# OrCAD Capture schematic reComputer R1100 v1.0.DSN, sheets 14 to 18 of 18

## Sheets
14 16 Gigabit PoE: size A3
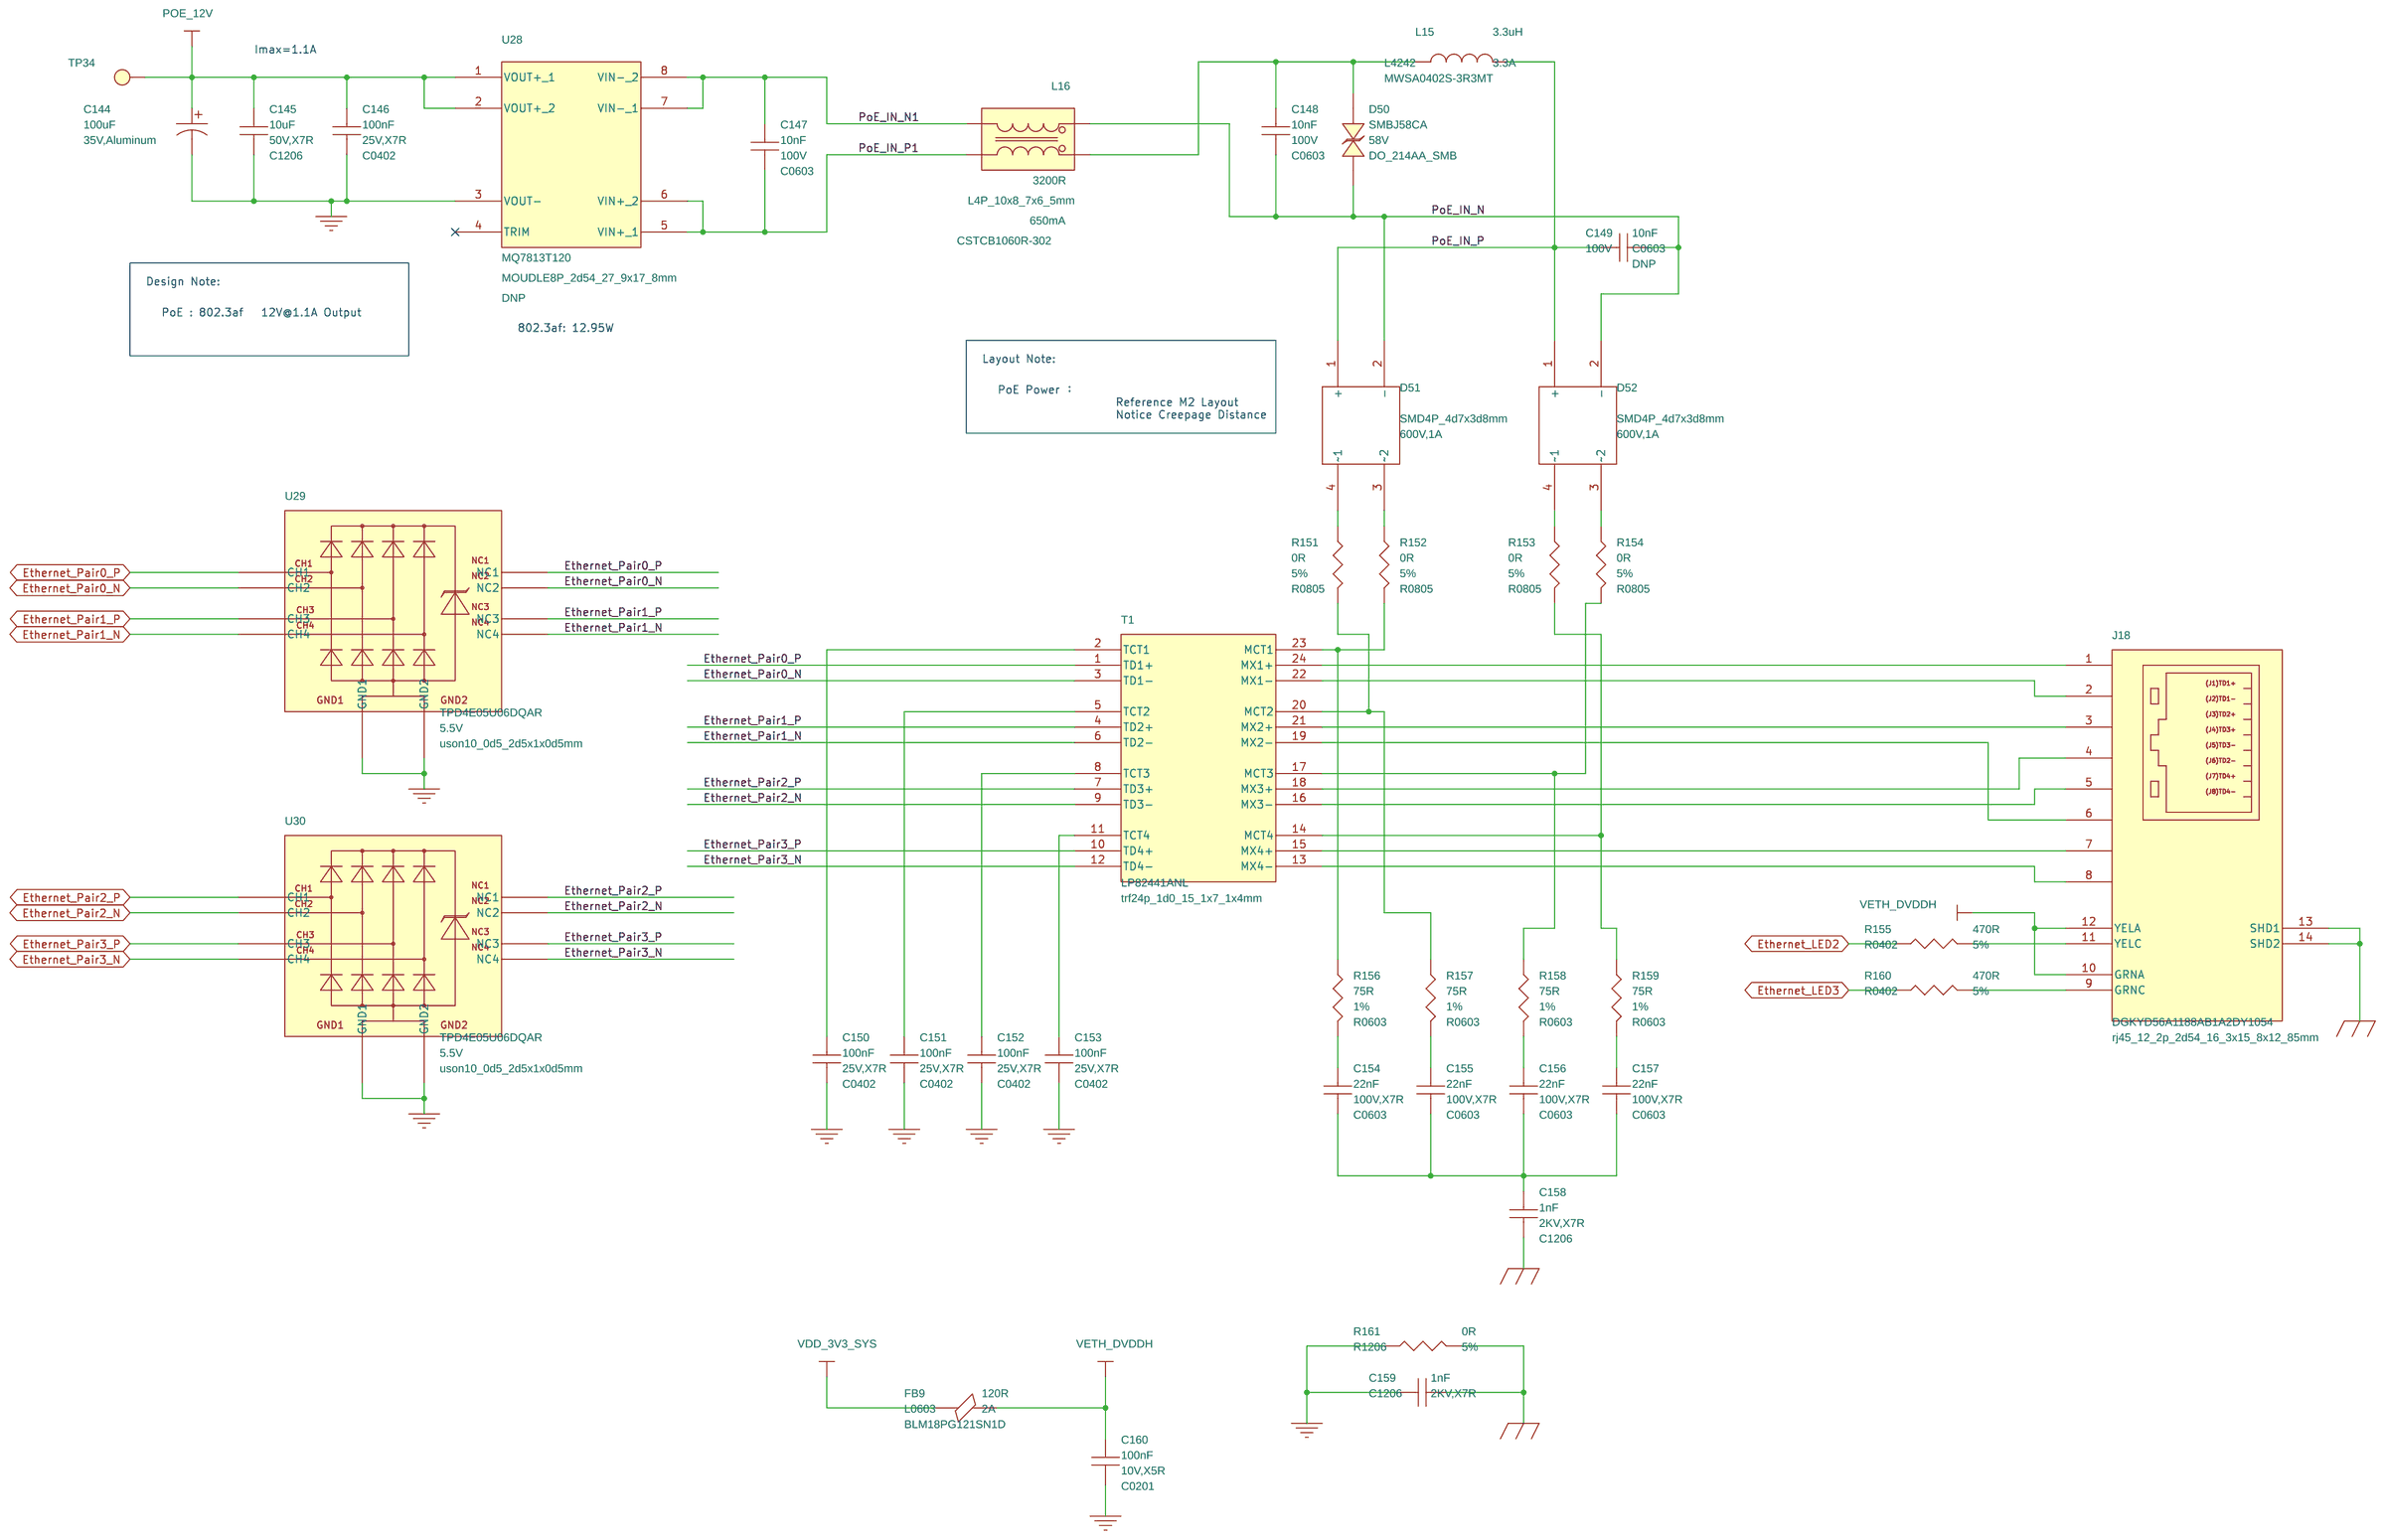
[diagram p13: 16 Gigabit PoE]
15 17 Terminal: size A3
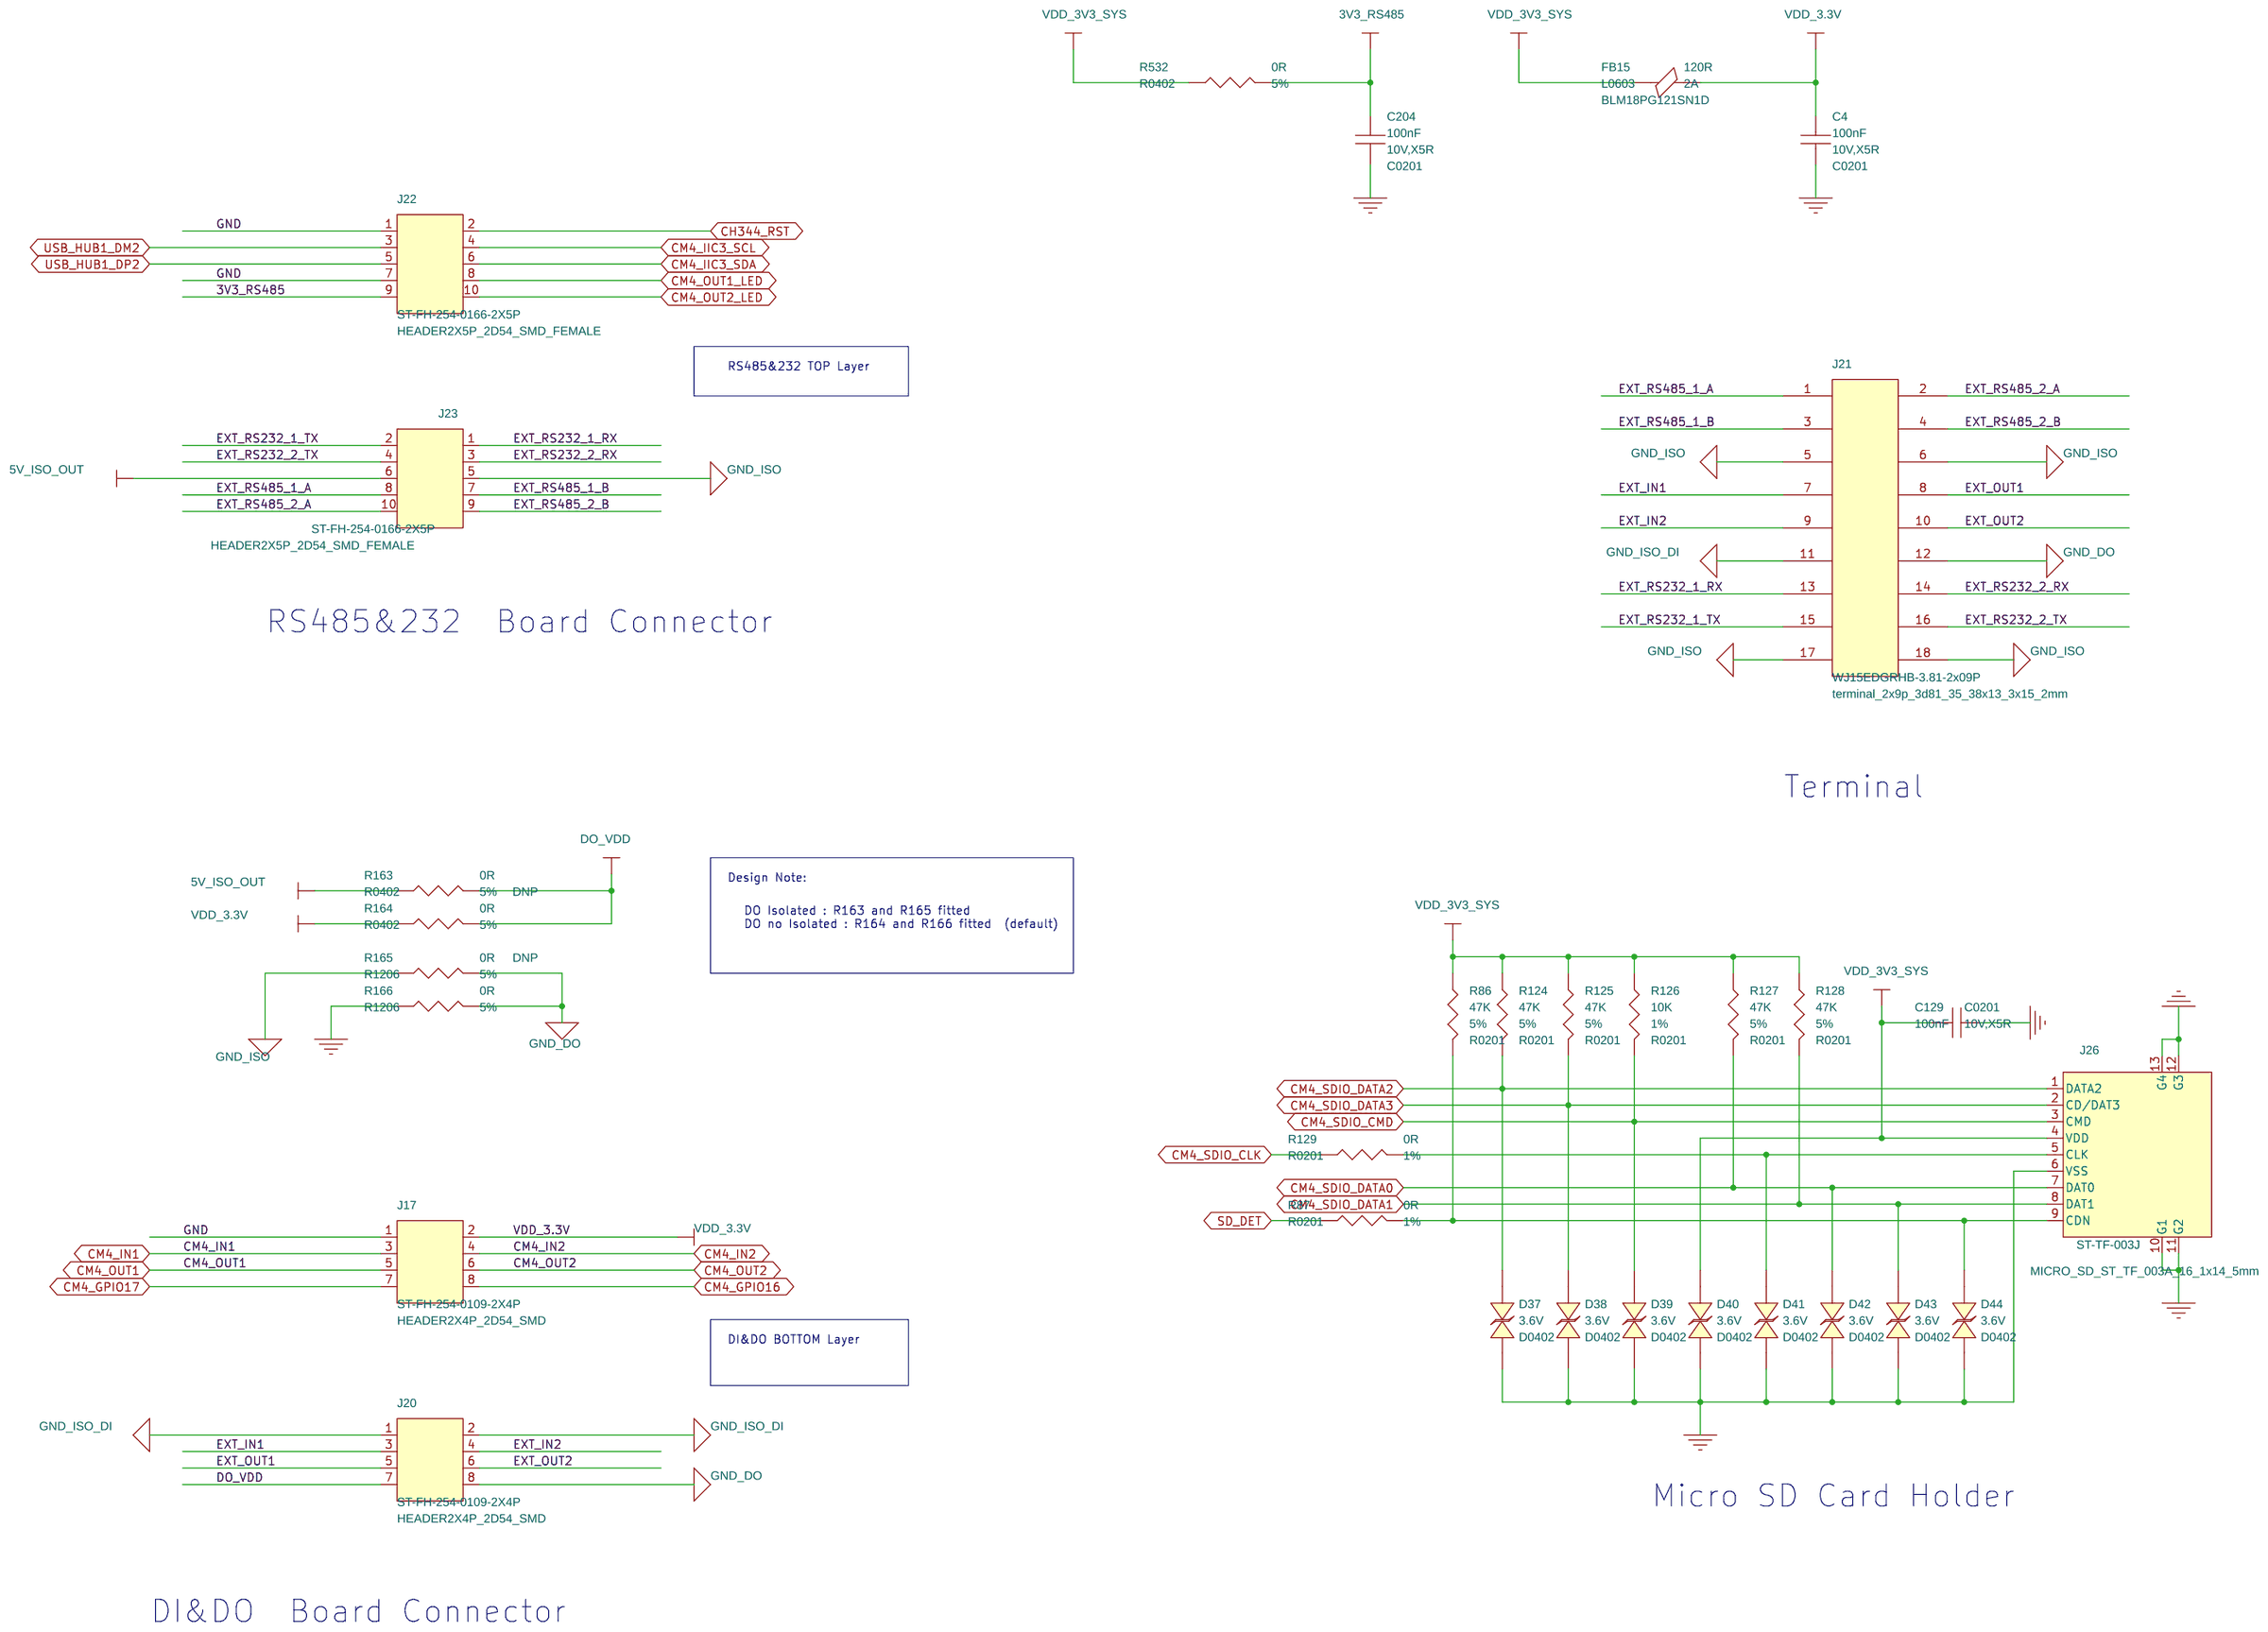
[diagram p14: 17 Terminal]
16 18 M.2 SSD: size A3
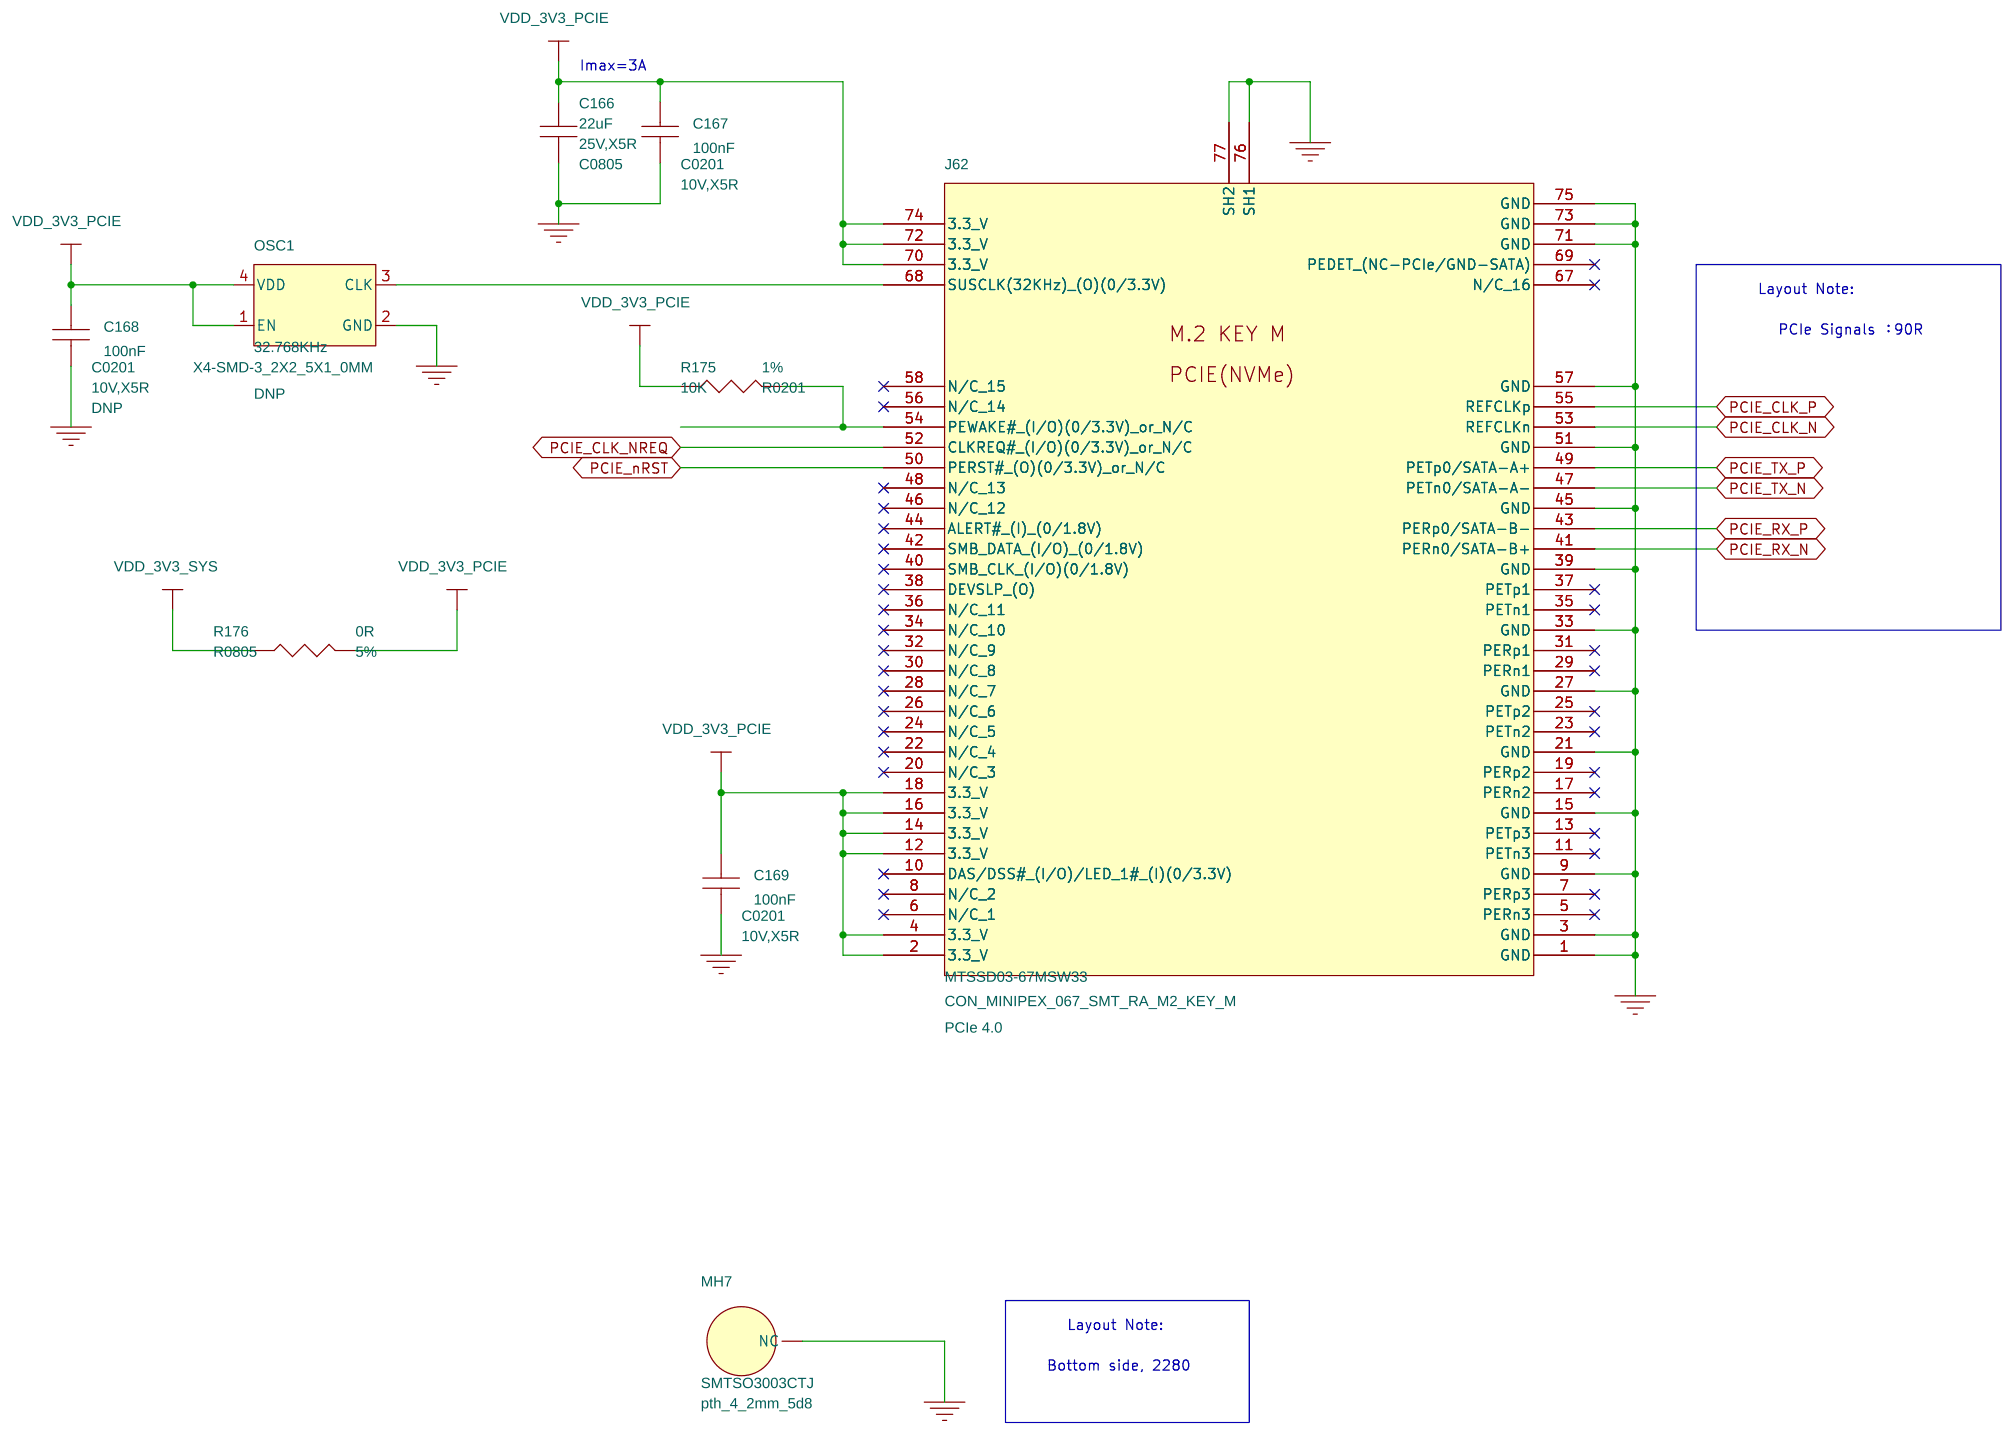
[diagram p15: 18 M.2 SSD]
17 01 Title / Revision History
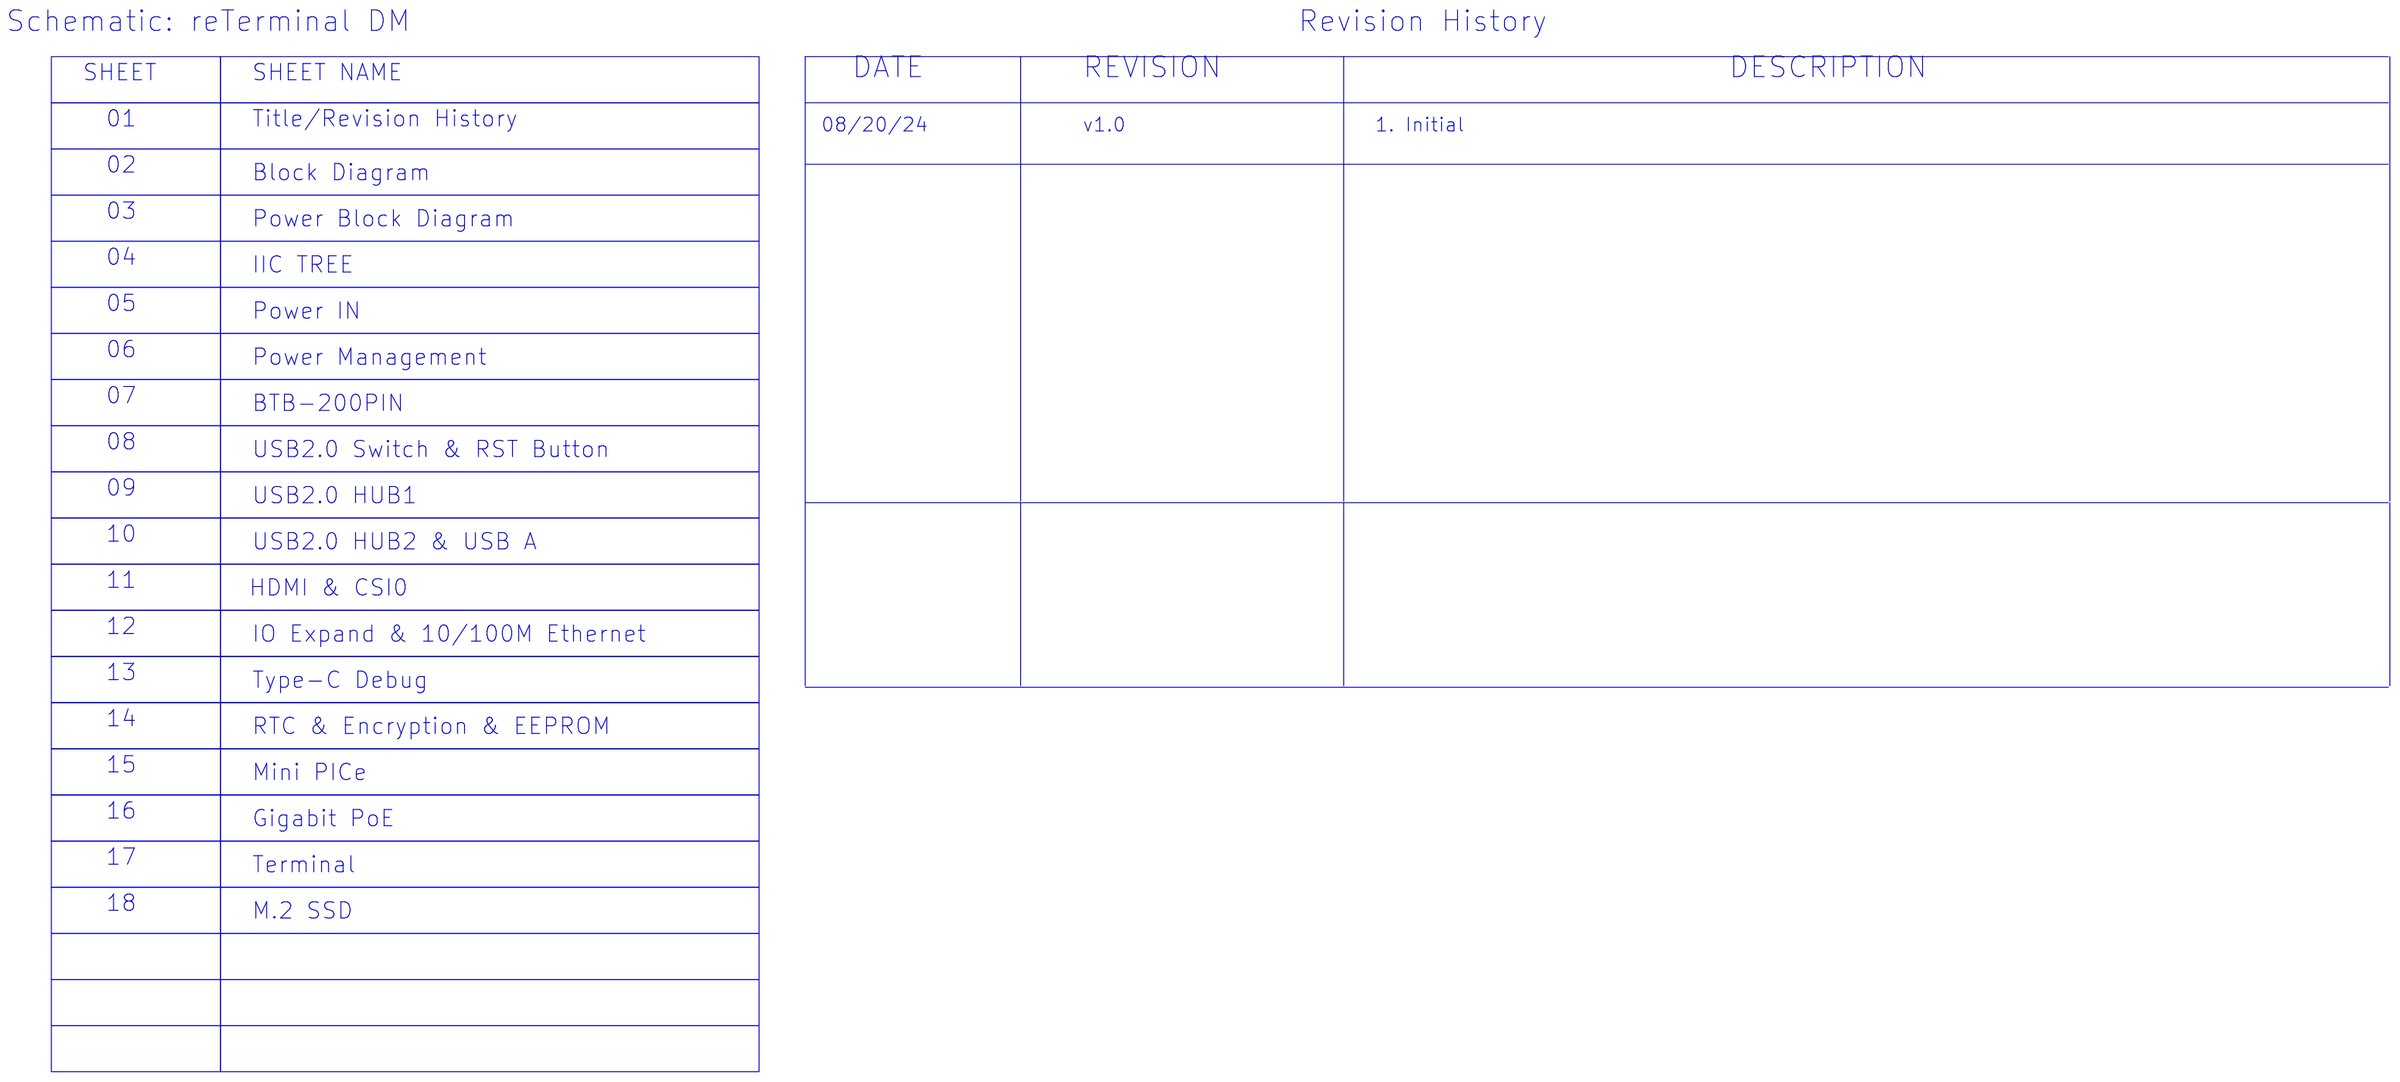
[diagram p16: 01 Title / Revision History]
18 12 IO Expan & 10/100M Ethernet: size A3
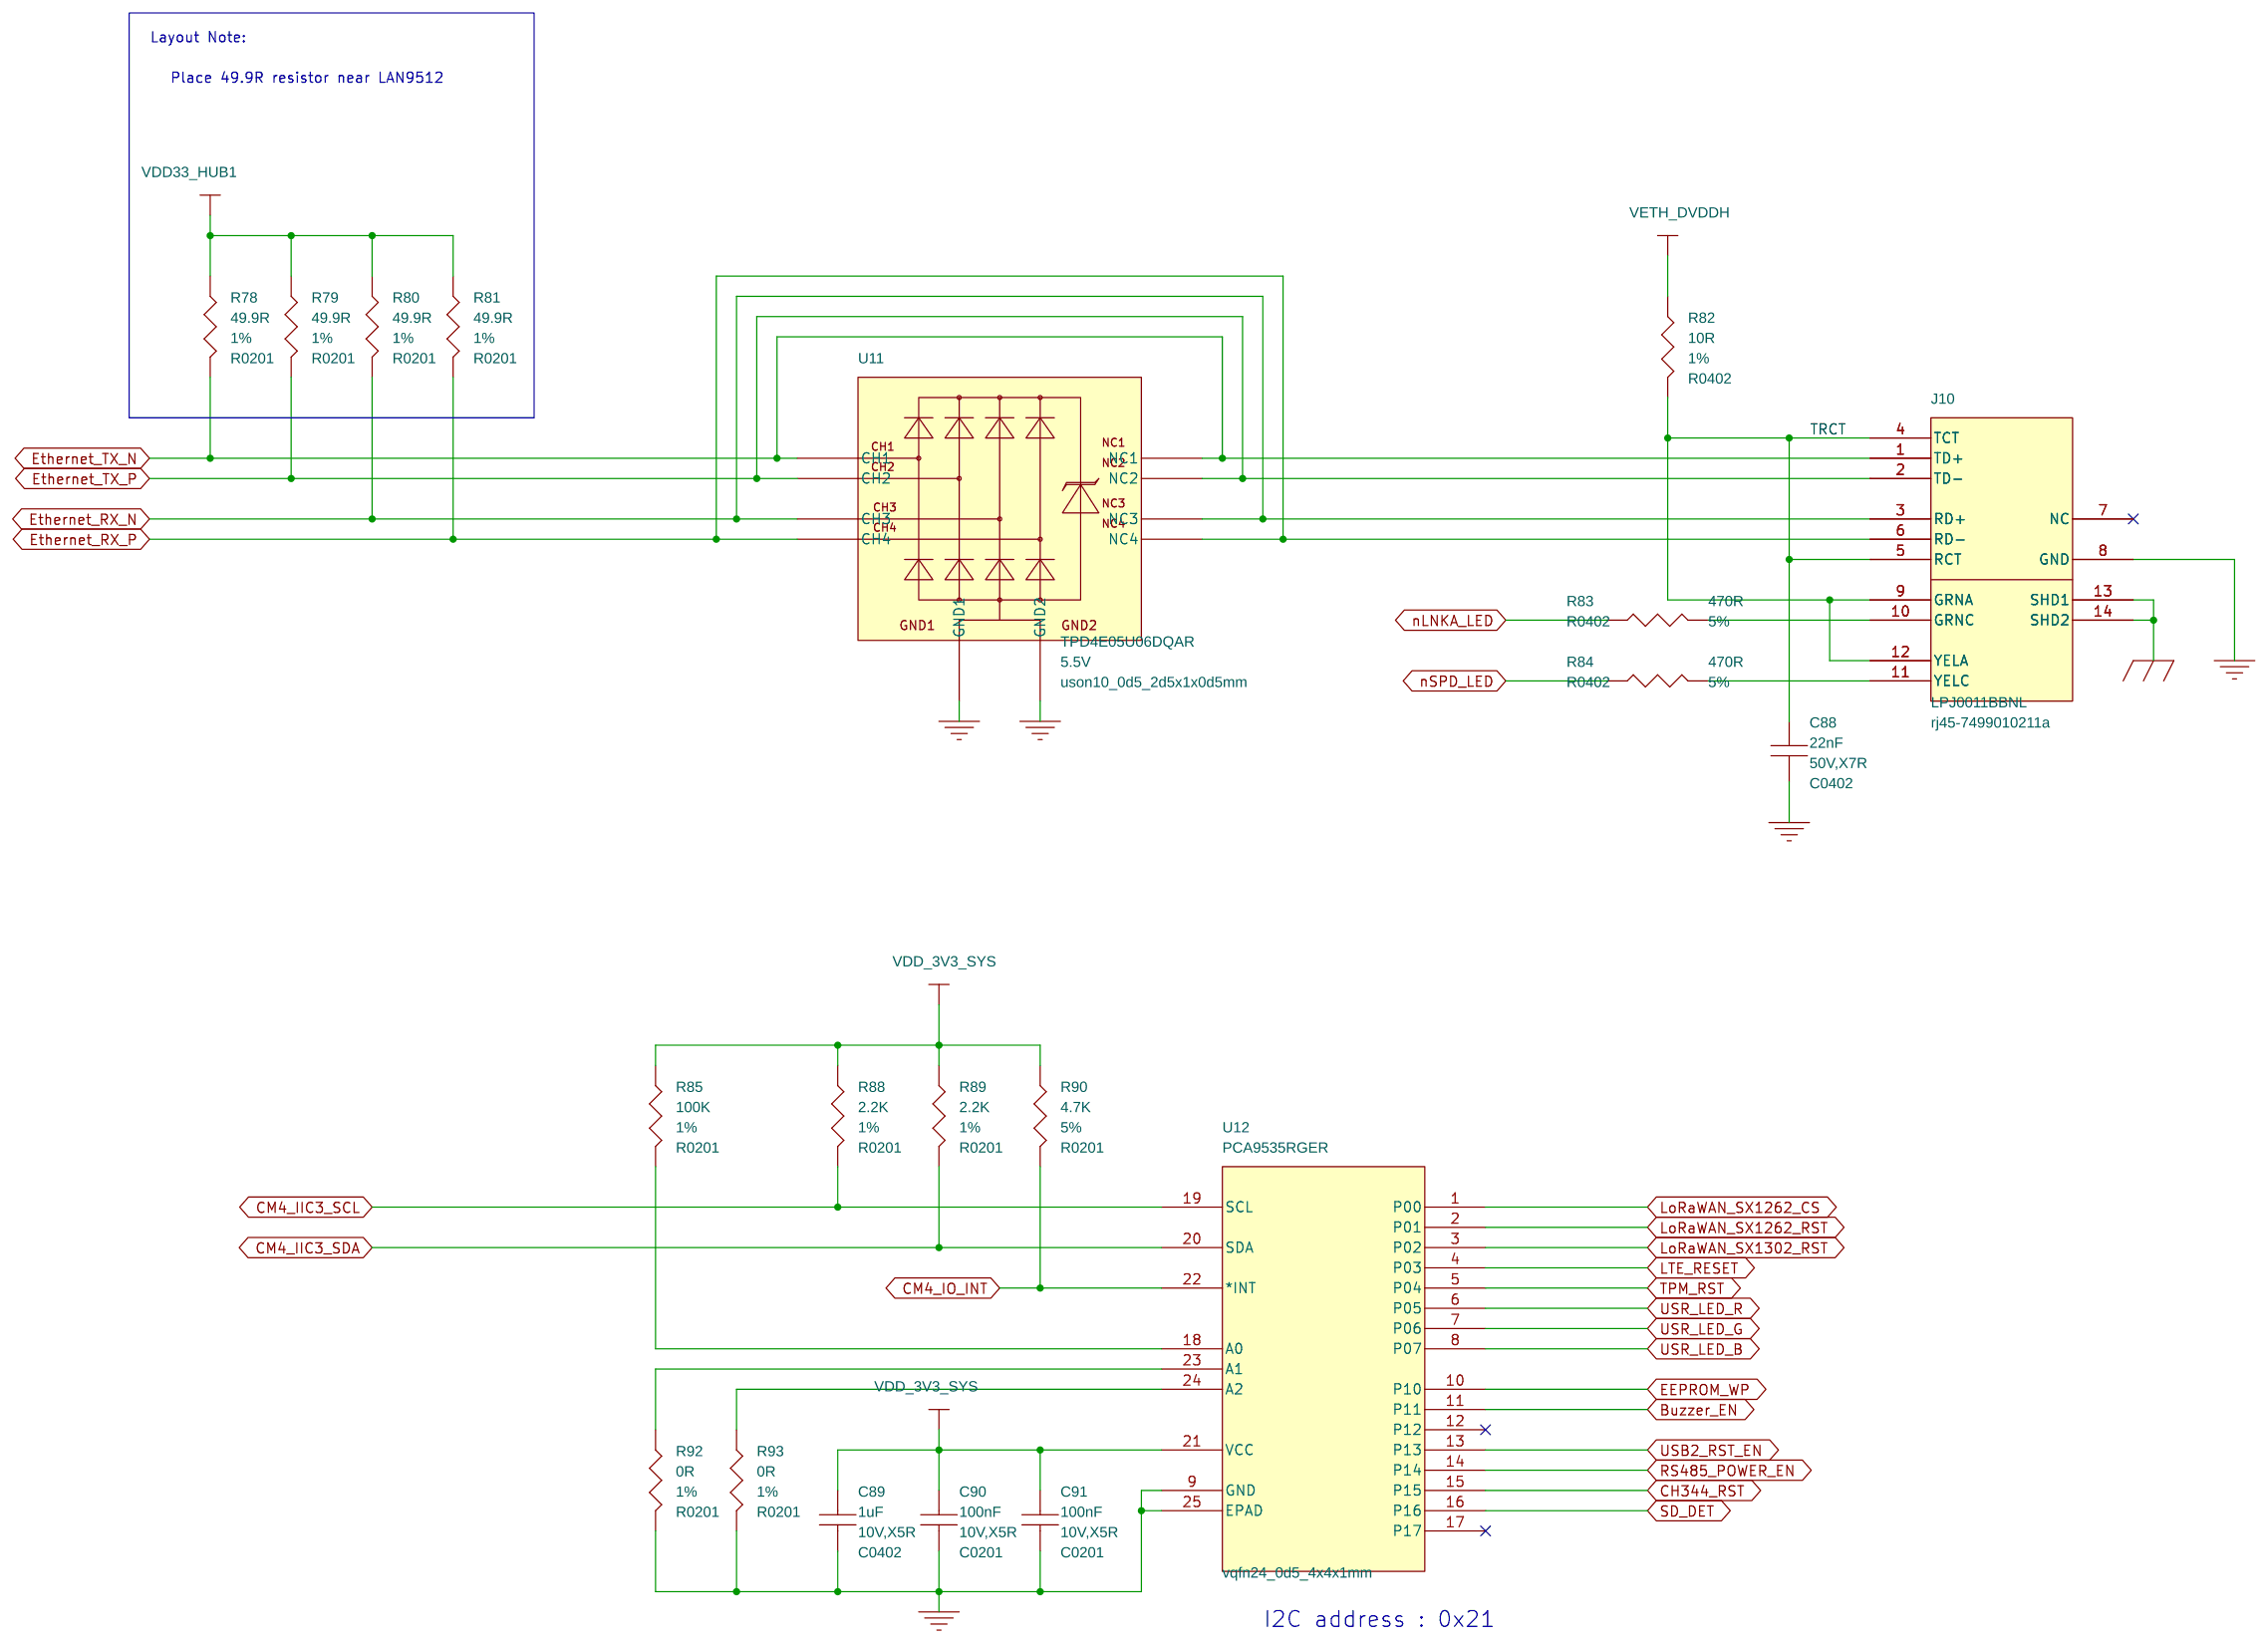
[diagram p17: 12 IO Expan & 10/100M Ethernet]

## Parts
sheet 12 IO Expan & 10/100M Ethernet
C88  22nF  [C0402]
C89  1uF  [C0402]
C90  100nF  [C0201]
C91  100nF  [C0201]
J10  LPJ0011BBNL  [rj45-7499010211a]
R78  49.9R  [R0201]
R79  49.9R  [R0201]
R80  49.9R  [R0201]
R81  49.9R  [R0201]
R82  10R  [R0402]
R83  470R  [R0402]
R84  470R  [R0402]
R85  100K  [R0201]
R88  2.2K  [R0201]
R89  2.2K  [R0201]
R90  4.7K  [R0201]
R92  0R  [R0201]
R93  0R  [R0201]
U11  TPD4E05U06DQAR  [uson10_0d5_2d5x1x0d5mm]
U12  PCA9535RGER  [vqfn24_0d5_4x4x1mm]
sheet 16 Gigabit PoE
C144  100uF  [Electro_SMD_6_6X6_6MM]
C145  10uF  [C1206]
C146  100nF  [C0402]
C147  10nF  [C0603]
C148  10nF  [C0603]
C149  10nF  [C0603]
C150  100nF  [C0402]
C151  100nF  [C0402]
C152  100nF  [C0402]
C153  100nF  [C0402]
C154  22nF  [C0603]
C155  22nF  [C0603]
C156  22nF  [C0603]
C157  22nF  [C0603]
C158  1nF  [C1206]
C159  1nF  [C1206]
C160  100nF  [C0201]
D50  SMBJ58CA  [DO_214AA_SMB]
D51  BRIDGE RECTIFIERS DF  [SMD4P_4d7x3d8mm]
D52  BRIDGE RECTIFIERS DF  [SMD4P_4d7x3d8mm]
FB9  120R  [L0603]
J18  DGKYD56A1188AB1A2DY1054  [rj45_12_2p_2d54_16_3x15_8x12_85mm]
L15  3.3uH  [L4242]
L16  3200R  [L4P_10x8_7x6_5mm]
R151  0R  [R0805]
R152  0R  [R0805]
R153  0R  [R0805]
R154  0R  [R0805]
R155  470R  [R0402]
R156  75R  [R0603]
R157  75R  [R0603]
R158  75R  [R0603]
R159  75R  [R0603]
R160  470R  [R0402]
R161  0R  [R1206]
T1  LP82441ANL  [trf24p_1d0_15_1x7_1x4mm]
TP34  Test Point  [TP35S_SMD]
U28  MQ7813T120  [MOUDLE8P_2d54_27_9x17_8mm]
U29  TPD4E05U06DQAR  [uson10_0d5_2d5x1x0d5mm]
U30  TPD4E05U06DQAR  [uson10_0d5_2d5x1x0d5mm]
sheet 17 Terminal
C4  100nF  [C0201]
C129  100nF  [C0201]
C204  100nF  [C0201]
D37  TPD1E1B04DPY  [D0402]
D38  TPD1E1B04DPY  [D0402]
D39  TPD1E1B04DPY  [D0402]
D40  TPD1E1B04DPY  [D0402]
D41  TPD1E1B04DPY  [D0402]
D42  TPD1E1B04DPY  [D0402]
D43  TPD1E1B04DPY  [D0402]
D44  TPD1E1B04DPY  [D0402]
FB15  120R  [L0603]
J17  ST-FH-254-0109-2X4P  [HEADER2X4P_2D54_SMD]
J20  ST-FH-254-0109-2X4P  [HEADER2X4P_2D54_SMD]
J21  WJ15EDGRHB-3.81-2x09P  [terminal_2x9p_3d81_35_38x13_3x15_2mm]
J22  ST-FH-254-0166-2X5P  [HEADER2X5P_2D54_SMD_FEMALE]
J23  ST-FH-254-0166-2X5P  [HEADER2X5P_2D54_SMD_FEMALE]
J26  ST-TF-003J  [MICRO_SD_ST_TF_003A_16_1x14_5mm]
R86  47K  [R0201]
R87  0R  [R0201]
R124  47K  [R0201]
R125  47K  [R0201]
R126  10K  [R0201]
R127  47K  [R0201]
R128  47K  [R0201]
R129  0R  [R0201]
R163  0R  [R0402]
R164  0R  [R0402]
R165  0R  [R1206]
R166  0R  [R1206]
R532  0R  [R0402]
sheet 18 M.2 SSD
C166  22uF  [C0805]
C167  100nF  [C0201]
C168  100nF  [C0201]
C169  100nF  [C0201]
J62  MTSSD03-67MSW33  [CON_MINIPEX_067_SMT_RA_M2_KEY_M]
MH7  SMTSO3003CTJ  [pth_4_2mm_5d8]
OSC1  32.768KHz  [X4-SMD-3_2X2_5X1_0MM]
R175  10K  [R0201]
R176  0R  [R0805]

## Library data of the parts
C88 = CC: SMD CAP Ceramic 22nF-50V-10%-X7R;0402; Manufacturer: YAGEO; Manufacturer Part Number: CC0402KRX7R9BB223; PN: 302010242; Package Size: 0402; Rating: 50V,X7R; Status: ST; Temperature: -55°C to 125°C
C89 = CC: SMD CAP Ceramic 1uF-10V-10%-X5R;0402; Manufacturer: YAGEO; Manufacturer Part Number: CC0402KRX5R6BB105; PN: 302010040; Package Size: 0402; Part Type: Ceramic; Rating: 10V,X5R; Status: BeagleBone Carrier Board; Temperature: -55°C to 85°C
C4 C90 C91 C160 C204 = CC: SMD CAP Ceramic 100nF-10V-10%-X5R;0201; CLASS: DISCRETE; Company Part Status: BeagleBone Carrier Board; Dielectric Type: Ceramic; Manufacturer: YAGEO; Manufacturer PN: CC0402KRX7R8BB104; Manufacturer Part Number: CC0201KRX5R6BB104; PN: 302010271; Package Size: 0201; Part Type: Ceramic; Rating: 10V,X5R; SIGNAL_MODEL: DEFAULT_CAPACITOR_100000pF_1_2; Status: ODYSSEY-i.MX8M; Temperature: -55°C to 85°C; Temperature Coefficient: X7R; Tolerance: 10%
J10 = RJ45_HanRun_HY911105T: DIP RJ45 W/P-10/100M;12P-21.25*15.93*13.3mm; Manufacturer: Link-PP; PN: 320140216; Status: Zola; Temperature: 0°C to 70°C
R78-R81 = R: SMD RES 49.9R-1%-1/20W;0201; Manufacturer: YAGEO; Manufacturer Part Number: RC0201FR-0749R9L; PN: 301012326; Package Size: 0201; Rating: 1%; Status: BeagleBone AI TDA4VM; Temperature: -55°C to 125°C
R82 = R: SMD RES 10R-1%-1/16W;0402; Manufacturer: YAGEO; Manufacturer Part Number: RC0402FR-0710RL; PN: 301010444; Package Size: 0402; Rating: 1%; Status: IOT Enabling Dongle Board; Temperature: -55°C to 155°C
R83 R84 R155 R160 = R: SMD RES 470R-5%-1/16W;0402; Manufacturer: YAGEO; Manufacturer Part Number: RC0402JR-07470RL; PN: 301010013; Part Type: RES; Priority: A; Rating: 5%; Status: BeagleBone AI TDA4VM; Temperature: -55°C to 155°C
R85 = R: SMD RES 100K-±1%-1/20W;0201; CLASS: DISCRETE; Company Part Status: BeagleBone Carrier Board; Manufacturer: YAGEO; Manufacturer PN: RC0402FR-07100KL; Manufacturer Part Number: RC0201FR-07100KL; PN: 301010765; Package Size: 0201; Part Type: RES; Rated Power: 1/16W; Rating: 1%; Status: LR1110; Temperature: -55°C to 125°C
R88 R89 = R: SMD RES 2.2K-1%-1/20W;0201; CLASS: DISCRETE; Company Part Status: BeagleBone Carrier Board; Manufacturer: YAGEO; Manufacturer PN: RC0402FR-074K7L; Manufacturer Part Number: RC0201FR-072K2L; PN: 301010753; Package Size: 0201; Part Type: RES; Rated Power: 1/16W; Rating: 1%; Status: BeagleBone AI TDA4VM; Temperature: -55°C to 125°C
R90 = R: SMD RES;4.7K-5%-1/20W;0201; CLASS: DISCRETE; Company Part Status: BeagleBone Carrier Board; Manufacturer: YAGEO; Manufacturer PN: RC0402FR-074K7L; Manufacturer Part Number: RC0201JR-074K7L; PN: 301010677; Package Size: 0201; Part Type: RES; Rated Power: 1/16W; Rating: 5%; Status: BeagleV-Ahead; Temperature: -55°C to 125°C
R92 R93 = R: SMD RES 0R-±1%-1/20W;0201; CLASS: DISCRETE; Company Part Status: BeagleBone Carrier Board; Manufacturer: YAGEO; Manufacturer PN: RC0402JR-070RL; Manufacturer Part Number: RC0201FR-070RL; PN: 301010525; Package Size: 0201; Part Type: RES; Rated Power: 1/16W; Rating: 1%; Status: BeagleBone AI TDA4VM; Temperature: -55°C to 125°C; Datasheet: Y:\01_Cadence_Library\05_Datasheet\301010000_YAGEO_RC0402JR-070RL_Datasheet.pdf
U11 U29 U30 = TPD4E05U06DQAR: SMD Diode Array ESD;4 Channel,6 Gbps,5.5V;USON-10; Manufacturer: TI; PN: 304060294; Part Type: ESD; Priority: A; Rating: 5.5V; Status: BeagleBone AI TDA4VM; Temperature: -40°C to 125°C
U12 = PCA9535RGE: SMD IC Interface;16-bit 2.3V to 5.5V I2C I/O expander with interrupt & config registers;VQFN(24); Manufacturer: TI; PN: 310071440; Status: reComputer Industrial J201; Temperature: -40°C to 85°C
C144 = CT: SMD CAP Aluminum 100uF-35V;D6.3*H7.7mm; Manufacturer: ST; Manufacturer Part Number: CS1V101M-CRE77; PN: 302030052; Part Type: Aluminum; Rating: 35V,Aluminum; Status: reTerminal DM
C145 = CC: SMD CAP Ceramic 10UF-50V-10%-X7R;1206; Manufacturer: Samsung; Manufacturer Part Number: CL31B106KBHNNNE; PN: 302012419; Part Type: Ceramic; Rating: 50V,X7R; Status: reTerminal DM; Temperature: -55°C to 125°C
C146 C150-C153 = CC: SMD CAP Ceramic 100nF-25V-10%-X7R;0402; Manufacturer: YAGEO; Manufacturer Part Number: CC0402KRX7R8BB104; PN: 302010024; Part Type: Ceramic; Rating: 25V,X7R; Status: BeagleBone Carrier Board; Temperature: -55°C to 125°C
C147 C148 = CC: SMD CAP Ceramic 10nF-100V-10%-X7R;0603; Manufacturer: YAGEO; Manufacturer Part Number: CC0603KRX7R0BB103; PN: 302012962; Part Type: Ceramic; Rating: 100V; Status: reTerminal Plus
C149 = CC: SMD CAP Ceramic 10nF-100V-10%-X7R;0603; ASSY: DNP; Manufacturer: YAGEO; Manufacturer Part Number: CC0603KRX7R0BB103; PN: 302012962; Part Type: Ceramic; Rating: 100V; Status: reTerminal Plus
C154-C157 = CC: SMD CAP Ceramic 22nF-100V-10%-X7R;0603; Manufacturer: TDK; Manufacturer Part Number: C1608X7R2A223K080AA; PN: 302010920; Part Type: Ceramic; Rating: 100V,X7R; Status: STM32MP135D
C158 C159 = CC: SMD CAP Ceramic 1nF-2kV-10%-X7R;1206; Manufacturer: YAGEO; Manufacturer Part Number: CC1206KKX7RDBB102; PN: 302011962; Part Type: Ceramic; Rating: 2KV,X7R; Status: Zola_Gateway; Temperature: -55°C to 125°C
D50 = DIODE_TVS_BI-DIR: SMD Diode TVS-58VWM-93.6V;DO-214AA(SMB); Manufacturer: 君耀; PN: 304050978; Part Type: TVS; Rating: 58V; Status: reTerminal DM; Temperature: -55°C to 150°C
D51 D52 = BRIDGE_RECTIFIERS_DF: SMD Diode;600V-1A-4P-7*4.9*3mm; Manufacturer: MDD; Manufacturer Part Number: MB6S; PN: 304010994; Rating: 600V,1A; Status: reTerminal Plus
FB9 FB15 = FB: SMD Ferrite Bead;120R-2A;0603; CLASS: DISCRETE; Company Part Status: BeagleBone Carrier Board; Manufacturer: Murata; Manufacturer PN: BLM18PG121SN1D; Manufacturer Part Number: BLM18PG121SN1D; PN: 303030024; Package Size: 0603; Part Type: Ferrite Bead; Rating: 2A; Status: BeagleBone Carrier Board; Temperature: -55°C to 125°C
J18 = RJ45_LPJE101AGNL: DIP RJ45 W/P;12+2P-L15.8*W16.3*H12.85mm; PN: TMP-563; Package Size: 12+2P-L15.8*W16.3*H12.85mm; Status: reComputer R1002; Temperature: -40°C to 85°C
L15 = L: SMD Inductor 3.3uH-20%-3.3A;2P-L4.2*W4.4*H1.8m; Manufacturer: Sunlord; Manufacturer Part Number: MWSA0402S-3R3MT; PN: 303011669; Part Type: Inductor; Rating: 3.3A
L16 = CLT: SMD Common Mode Filter;3200R-0.65A;4P-L8.7*W10*H6.5mm; Manufacturer: CODACA; Manufacturer Part Number: CSTCB1060R-302; PN: 303050383; Part Type: Common Mode Filter; Rating: 650mA
R151-R154 R176 = R: SMD RES 0R-5%-1/8W;0805; Manufacturer: YAGEO; Manufacturer Part Number: RC0805JR-070RL; PN: 301010359; Part Type: RES; Rating: 5%; Status: Sensecap Gateway V1; Temperature: -55°C to 155°C
R156-R159 = R: SMD RES 75R-1%-1/10W;0603; Manufacturer: YAGEO; Manufacturer Part Number: RC0603FR-0775RL; PN: 301010269; Part Type: RES; Rating: 1%; Status: STM32MP135D; Temperature: -55°C to 155°C
R161 = R: SMD RES 0R-5%-1/4W;1206; Manufacturer: YAGEO; Manufacturer Part Number: RC1206JR-070RL; PN: 301010407; Part Type: RES; Rating: 5%; Status: Sensecap Gateway V1; Temperature: -55°C to 155°C
T1 = LP82441ANL: SMD Transformer;24P-L15.1*W10.0*H4.0mm; Manufacturer: LINK-PP; PN: 303060374; Package Size: 24P-L15.1*W10.0*H4.0mm; Status: R2; Temperature: -40°C to 125°C
TP34 = Test_Point: Test Point;TP35S_SMD; CLASS: DISCRETE; Company Part Status: Mini-Gateway; Status: Mini-Gateway
U28 = Module_MQ7813: DIP PoE module;8P-2.54mm-L27.9*W17.8*H12.7mm; ASSY: DNP; Manufacturer: 英联; PN: 317990750; Rating: 12V,1.1A; Status: SenseCAP M2
C129 C167 C169 = CC: SMD CAP Ceramic 100nF-10V-10%-X5R;0201; Manufacturer: YAGEO; Manufacturer Part Number: CC0201KRX5R6BB104; PN: 302010271; Package Size: 0201; Part Type: Ceramic; Rating: 10V,X5R; Status: ODYSSEY-i.MX8M; Temperature: -55°C to 85°C
D37-D44 = DIODE_TVS_BI-DIR: SMD TVS DIODE 3.6V-6.4V-1pF;X1SON(2); Manufacturer: TI; Manufacturer Part Number: TPD1E1B04DPYR/T; PN: 304050798; Part Type: ESD; Rating: 3.6V; Status: Grove Base Cape for PocketBeagle; Temperature: -40°C to 125°C
J17 J20 = Header_2X4: SMD Black Female Header;2*4P-2.54-3.5mm; Manufacturer: 思拓展; PN: 320031625; Package Size: 2*4P-2.54-3.5mm; Status: reComputer Jetson J202; Temperature: -40°C to 105°C
J21 = Terminal_2X9: DIP Female Screw Terminal-Green;2*9P-3.81; Manufacturer: WANJIE; PN: TMP-728; Package Size: 3.81mm-90D; Status: reComputer R1100; Temperature: -40°C to 105°C
J22 J23 = Header_2X5: SMD Black Female Header ;2*5P-2.54-8.0mm; Manufacturer: 思拓展; PN: 320031587; Package Size: 2*5P-2.54-8.0mm; Status: reComputer R1100; Temperature: -40°C to 105°C
J26 = MicroSD_Card_9+4P: SMD SD Card Holder;9P-L14.7*W13.8*H1.0mm; Manufacturer: SUNGTECH; PN: 320090000; Package Size: 9P-L14.7*W13.8*H1.0mm; Status: Eagleye 310s
R86 R124 R125 R127 R128 = R: SMD RES;47K-5%-1/20W;0201; Manufacturer: YAGEO; Manufacturer Part Number: RC0201JR-0747KL; PN: 301010678; Package Size: 0201; Rating: 5%; Status: BeagleBone AI TDA4VM; Temperature: -55°C to 125°C
R87 R129 = R: SMD RES 0R-±1%-1/20W;0201; Manufacturer: YAGEO; Manufacturer Part Number: RC0201FR-070RL; PN: 301010525; Package Size: 0201; Part Type: RES; Rating: 1%; Status: BeagleBone AI TDA4VM; Temperature: -55°C to 125°C; Datasheet: Y:\01_Cadence_Library\05_Datasheet\301010000_YAGEO_RC0402JR-070RL_Datasheet.pdf
R126 R175 = R: SMD RES 10K-±1%-1/20W;0201; Manufacturer: YAGEO; Manufacturer Part Number: RC0201FR-0710KL; PN: 301010526; Package Size: 0201; Part Type: RES; Rating: 1%; Status: BeagleBone AI TDA4VM; Temperature: -55°C to 125°C
R163 = R: SMD RES 0R-5%-1/16W;0402; ASSY: DNP; Manufacturer: YAGEO; Manufacturer Part Number: RC0402JR-070RL; PN: 301010000; Part Type: RES; Rating: 5%; Status: BeagleBone Carrier Board; Temperature: -55°C to 155°C; Datasheet: Y:\01_Cadence_Library\05_Datasheet\301010000_YAGEO_RC0402JR-070RL_Datasheet.pdf
R164 = R: SMD RES 0R-5%-1/16W;0402; Manufacturer: YAGEO; Manufacturer Part Number: RC0402JR-070RL; PN: 301010000; Part Type: RES; Rating: 5%; Status: BeagleBone Carrier Board; Temperature: -55°C to 155°C; Datasheet: Y:\01_Cadence_Library\05_Datasheet\301010000_YAGEO_RC0402JR-070RL_Datasheet.pdf
R165 = R: SMD RES 0R-5%-1/4W;1206; ASSY: DNP; Manufacturer: YAGEO; Manufacturer Part Number: RC1206JR-070RL; PN: 301010407; Part Type: RES; Rating: 5%; Status: BeagleBone Carrier Board; Temperature: -55°C to 155°C
R166 = R: SMD RES 0R-5%-1/4W;1206; Manufacturer: YAGEO; Manufacturer Part Number: RC1206JR-070RL; PN: 301010407; Part Type: RES; Rating: 5%; Status: BeagleBone Carrier Board; Temperature: -55°C to 155°C
R532 = R: SMD RES 0R-5%-1/16W;0402; Manufacturer: YAGEO; Manufacturer Part Number: RC0402JR-070RL; PN: 301010000; Package Size: 0402; Rating: 5%; Status: BeagleBone Carrier Board; Temperature: -55°C to 155°C
C166 = CC: SMD CAP Ceramic 22uF-25V-20%-X5R;0805; Manufacturer: SAMSUNG; Manufacturer Part Number: CL21A226MAYNNNE; PN: 302013260; Package Size: 0805; Rating: 25V,X5R; Status: reServer Jetson Orin; Temperature: -55°C to 85°C
C168 = CC: SMD CAP Ceramic 100nF-10V-10%-X5R;0201; ASSY: DNP; Manufacturer: YAGEO; Manufacturer Part Number: CC0201KRX5R6BB104; PN: 302010271; Package Size: 0201; Part Type: Ceramic; Rating: 10V,X5R; Status: ODYSSEY-i.MX8M; Temperature: -55°C to 85°C
J62 = PCIe_M.2_Key_M_75Pin: SMD Connector Black M.2 Key-M,PCIe Gen4.0,H=3.0mm,10u Gold Plating;67P-0.5mm; Manufacturer: SUNGTECH; Manufacturer Part Number: ST-NG-032M; PN: 320112116; Package Size: L21.85*W7.15*H3.0; Rating: PCIe 4.0; Status: rpi5NVME; Temperature: -40°C to 80°C
MH7 = MHole: SMD Stud; M3铜柱, D5.56*0.3mm, 黄铜, 表面电镀锡(编带包装,带麦拉); FPLIST: pth_4_2mm_5d8,pth_4_2mm_5d8_top; Manufacturer: 雄和远景; PN: 326051030; Status: Jetson-20-2
OSC1 = OSC_4P: SMD Oscillator;32.768KHz-3.3V-30ppm;SMD-3225-4P-L3.2*W2.5*H1.1mm; ASSY: DNP; Manufacturer: Interquip; Manufacturer Part Number: 1631-L3273-BTBQYA; PN: 306020781; Part Type: Oscillator; Priority: A; Rating: 3.3V,30ppm; Status: Jetson-20-2; Temperature: -40°C to 85°C

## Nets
3V3_RS485: C204.1 J22.9 R532.2
5V_ISO_OUT: J23.6 R163.1 ; also on sheet 5
GND: C4.2 C88.2 C89.2 C90.2 C91.2 C129.1 C144.2 C145.2 C146.2 C150.2 C151.2 C152.2 C153.2 C159.1 C160.2 C166.2 C167.2 C168.2 C169.2 C204.2 D37.1 D38.1 D39.1 D40.1 D41.1 D42.1 D43.1 D44.1 J10.8(GND) J17.1 J22.1 J22.7 J26.6(VSS) J26.10(G1) J26.11(G2) J26.12(G3) J26.13(G4) J62.1(GND) J62.3(GND) J62.9(GND) J62.15(GND) J62.21(GND) J62.27(GND) J62.33(GND) J62.39(GND) J62.45(GND) J62.51(GND) J62.57(GND) J62.71(GND) J62.73(GND) J62.75(GND) J62.76(SH1) J62.77(SH2) MH7.1(NC) OSC1.2(GND) R92.2 R93.2 R161.1 R166.1 U11.3(GND1) U11.8(GND2) U12.9(GND) U12.25(EPAD) U28.3(VOUT-) U29.3(GND1) U29.8(GND2) U30.3(GND1) U30.8(GND2) ; also on sheet 4 5 6 7 8 9 10 11 12 13
GND_DO: J20.8 J21.12 R165.2 R166.2
GND_EARTH: C158.2 C159.2 J10.13(SHD1) J10.14(SHD2) J18.13(SHD1) J18.14(SHD2) R161.2 ; also on sheet 4 7 9 10 11
GND_ISO: J21.5 J21.6 J21.17 J21.18 J23.5 R165.1 ; also on sheet 5
GND_ISO_DI: J20.1 J20.2 J21.11
VDD33_HUB1: R78.1 R79.1 R80.1 R81.1 ; also on sheet 8
VDD_3.3V: C4.1 FB15.2 J17.2 R164.1
VDD_3V3_PCIe: C166.1 C167.1 C168.1 C169.1 J62.2(3.3_V) J62.4(3.3_V) J62.12(3.3_V) J62.14(3.3_V) J62.16(3.3_V) J62.18(3.3_V) J62.70(3.3_V) J62.72(3.3_V) J62.74(3.3_V) OSC1.1(EN) OSC1.4(VDD) R175.1 R176.2
VDD_3V3_SYS: C89.1 C90.1 C91.1 C129.2 D40.2 FB9.1 FB15.1 J26.4(VDD) R85.1 R86.1 R88.1 R89.1 R90.1 R124.1 R125.1 R126.1 R127.1 R128.1 R176.1 R532.1 U12.21(VCC) ; also on sheet 4 5 7 8 9 10 11 12 13
Buzzer_EN: U12.11(P11) ; also on sheet 7
CH344_RST: J22.2 U12.15(P15)
CM4_GPIO16: J17.8 ; also on sheet 6
CM4_GPIO17: J17.7 ; also on sheet 6
CM4_IIC3_SCL: J22.4 R88.2 U12.19(SCL) ; also on sheet 6 13
CM4_IIC3_SDA: J22.6 R89.2 U12.20(SDA) ; also on sheet 6 13
CM4_IN1: J17.3 ; also on sheet 6 7
CM4_IN2: J17.4 ; also on sheet 6 7
CM4_IO_INT: R90.2 U12.22(*INT) ; also on sheet 6
CM4_OUT1: J17.5 ; also on sheet 6 7
CM4_OUT1_LED: J22.8 ; also on sheet 7
CM4_OUT2: J17.6 ; also on sheet 6 7
CM4_OUT2_LED: J22.10 ; also on sheet 7
CM4_SDIO_CLK: R129.1 ; also on sheet 6
CM4_SDIO_CMD: D39.2 J26.3(CMD) R126.2 ; also on sheet 6
CM4_SDIO_DATA0: D42.2 J26.7(DAT0) R127.2 ; also on sheet 6
CM4_SDIO_DATA1: D43.2 J26.8(DAT1) R128.2 ; also on sheet 6
CM4_SDIO_DATA2: D37.2 J26.1(DATA2) R124.2 ; also on sheet 6
CM4_SDIO_DATA3: D38.2 J26.2(CD/DAT3) R125.2 ; also on sheet 6
DO_VDD: J20.7 R163.2 R164.2
EEPROM_WP: U12.10(P10) ; also on sheet 12
Ethernet_LED2: R155.1 ; also on sheet 6
Ethernet_LED3: R160.1 ; also on sheet 6
Ethernet_Pair0_N: T1.3(TD1-) U29.2(CH2) U29.9(NC2) ; also on sheet 6
Ethernet_Pair0_P: T1.1(TD1+) U29.1(CH1) U29.10(NC1) ; also on sheet 6
Ethernet_Pair1_N: T1.6(TD2-) U29.5(CH4) U29.6(NC4) ; also on sheet 6
Ethernet_Pair1_P: T1.4(TD2+) U29.4(CH3) U29.7(NC3) ; also on sheet 6
Ethernet_Pair2_N: T1.9(TD3-) U30.2(CH2) U30.9(NC2) ; also on sheet 6
Ethernet_Pair2_P: T1.7(TD3+) U30.1(CH1) U30.10(NC1) ; also on sheet 6
Ethernet_Pair3_N: T1.12(TD4-) U30.5(CH4) U30.6(NC4) ; also on sheet 6
Ethernet_Pair3_P: T1.10(TD4+) U30.4(CH3) U30.7(NC3) ; also on sheet 6
Ethernet_RX_N: J10.3(RD+) R80.2 U11.4(CH3) U11.7(NC3) ; also on sheet 8
Ethernet_RX_P: J10.6(RD-) R81.2 U11.5(CH4) U11.6(NC4) ; also on sheet 8
Ethernet_TX_N: J10.1(TD+) R78.2 U11.1(CH1) U11.10(NC1) ; also on sheet 8
Ethernet_TX_P: J10.2(TD-) R79.2 U11.2(CH2) U11.9(NC2) ; also on sheet 8
EXT_IN1: J20.3 J21.7
EXT_IN2: J20.4 J21.9
EXT_OUT1: J20.5 J21.8
EXT_OUT2: J20.6 J21.10
EXT_RS232_1_RX: J21.13 J23.1
EXT_RS232_1_TX: J21.15 J23.2
EXT_RS232_2_RX: J21.14 J23.3
EXT_RS232_2_TX: J21.16 J23.4
EXT_RS485_1_A: J21.1 J23.8
EXT_RS485_1_B: J21.3 J23.7
EXT_RS485_2_A: J21.2 J23.10
EXT_RS485_2_B: J21.4 J23.9
LoRaWAN_SX1262_CS: U12.1(P00) ; also on sheet 13
LoRaWAN_SX1262_RST: U12.2(P01) ; also on sheet 13
LoRaWAN_SX1302_RST: U12.3(P02) ; also on sheet 13
LTE_RESET: U12.4(P03) ; also on sheet 13
nLNKA_LED: R83.1 ; also on sheet 8
nSPD_LED: R84.1 ; also on sheet 8
PCIE_CLK_N: J62.53(REFCLKn) ; also on sheet 6
PCIE_CLK_NREQ: J62.52(CLKREQ#_(I/O)(0/3.3V)_or_N/C) ; also on sheet 6
PCIE_CLK_P: J62.55(REFCLKp) ; also on sheet 6
PCIE_nRST: J62.50(PERST#_(O)(0/3.3V)_or_N/C) ; also on sheet 6
PCIE_RX_N: J62.41(PERn0/SATA-B+) ; also on sheet 6
PCIE_RX_P: J62.43(PERp0/SATA-B-) ; also on sheet 6
PCIE_TX_N: J62.47(PETn0/SATA-A-) ; also on sheet 6
PCIE_TX_P: J62.49(PETp0/SATA-A+) ; also on sheet 6
PoE_12V: C144.1 C145.1 C146.1 TP34.1(TP) U28.1(VOUT+) U28.2(VOUT+) ; also on sheet 4
PoE_IN_N: C148.2 C149.2 D50.1 D51.2(-) D52.2(-) L16.1
PoE_IN_N1: C147.1 L16.4 U28.7(VIN-_1) U28.8(VIN-_2)
PoE_IN_P: C149.1 D51.1(+) D52.1(+) L15.2
PoE_IN_P1: C147.2 L16.3 U28.5(VIN+_1) U28.6(VIN+_2)
RS485_POWER_EN: U12.14(P14) ; also on sheet 5
SD_DET: R87.1 U12.16(P16)
TPM_RST: U12.5(P04) ; also on sheet 12
TRCT: C88.1 J10.4(TCT) J10.5(RCT) J10.9(GRNA) J10.12(YELA) R82.2
USB2_RST_EN: U12.13(P13) ; also on sheet 9
USB_HUB1_DM2: J22.3 ; also on sheet 8
USB_HUB1_DP2: J22.5 ; also on sheet 8
USR_LED_B: U12.8(P07) ; also on sheet 7
USR_LED_G: U12.7(P06) ; also on sheet 7
USR_LED_R: U12.6(P05) ; also on sheet 7
VETH_DVDDH: C160.1 FB9.2 J18.10(GRNA) J18.12(YELA) R82.1
N22026897: J18.1 T1.24(MX1+)
N22026906: J18.2 T1.22(MX1-)
N22026915: J18.3 T1.21(MX2+)
N22026957: J18.7 T1.15(MX4+)
N22026966: J18.8 T1.13(MX4-)
N22027038: R153.2 R159.1 T1.14(MCT4)
N22027110: R151.2 R157.1 T1.20(MCT2)
N22027117: R154.2 R158.1 T1.17(MCT3)
N22027433: J18.11(YELC) R155.2
N22027462: J18.9(GRNC) R160.2
N22028382: R152.2 R156.1 T1.23(MCT1)
N22028488: D52.4(~1) R153.1
N22028491: D52.3(~2) R154.1
N22029929: C148.1 D50.2 L15.1 L16.2
N22030276: D51.4(~1) R151.1
N22030277: D51.3(~2) R152.1
N22038029: C154.1 R156.2
N22038032: C154.2 C155.2 C156.2 C157.2 C158.1
N22038068: C155.1 R157.2
N22038120: C156.1 R158.2
N22038172: C157.1 R159.2
N22078660: J18.6 T1.19(MX2-)
N22078676: J18.5 T1.16(MX3-)
N22078685: J18.4 T1.18(MX3+)
N22567639: C153.1 T1.11(TCT4)
N22567644: C152.1 T1.8(TCT3)
N22567654: C151.1 T1.5(TCT2)
N22567659: C150.1 T1.2(TCT1)
N23463209: J10.10(GRNC) R83.2
N23463212: J10.11(YELC) R84.2
N23466024: R85.2 U12.18(A0)
N23466170: R92.1 U12.23(A1)
N23466179: R93.1 U12.24(A2)
N23500588: J62.68(SUSCLK(32KHz)_(O)(0/3.3V)) OSC1.3(CLK)
N23502047: J62.54(PEWAKE#_(I/O)(0/3.3V)_or_N/C) R175.2
N24049462: D41.2 J26.5(CLK) R129.2
N24050469: D44.2 J26.9(CDN) R86.2 R87.2

Not connected (* = marked no-connect by the designer): J10 7(NC)*; J62 5(PERn3)* 6(N/C_1)* 7(PERp3)* 8(N/C_2)* 10(DAS/DSS#_(I/O)/LED_1#_(I)(0/3.3V))* 11(PETn3)* 13(PETp3)* 17(PERn2)* 19(PERp2)* 20(N/C_3)* 22(N/C_4)* 23(PETn2)* 24(N/C_5)* 25(PETp2)* 26(N/C_6)* 28(N/C_7)* 29(PERn1)* 30(N/C_8)* 31(PERp1)* 32(N/C_9)* 34(N/C_10)* 35(PETn1)* 36(N/C_11)* 37(PETp1)* 38(DEVSLP_(O))* 40(SMB_CLK_(I/O)(0/1.8V))* 42(SMB_DATA_(I/O)_(0/1.8V))* 44(ALERT#_(I)_(0/1.8V))* 46(N/C_12)* 48(N/C_13)* 56(N/C_14)* 58(N/C_15)* 67(N/C_16)* 69(PEDET_(NC-PCIe/GND-SATA))*; U12 12(P12)* 17(P17)*; U28 4(TRIM)*

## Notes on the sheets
sheet 14
- Imax=1.1A
- Design Note:
- PoE : 802.3af   12V@1.1A Output
- 802.3af: 12.95W
- Layout Note:
- PoE Power ：
                      Reference M2 Layout
                      Notice Creepage Distance
sheet 15
- RS485&232 TOP Layer
- RS485&232  Board Connector
- Terminal
- Design Note:
- DO Isolated : R163 and R165 fitted
  DO no Isolated : R164 and R166 fitted  (default)
- DI&DO BOTTOM Layer
- Micro SD Card Holder
- DI&DO  Board Connector
sheet 16
- Imax=3A
- Layout Note:
- PCIe Signals ：90R
- Layout Note:
- Bottom side, 2280
sheet 17
- Schematic: reTerminal DM
- Revision History
- SHEET
- SHEET NAME
- DATE
- REVISION
- DESCRIPTION
- 01
- Title/Revision History
- 08/20/24
- v1.0
- 1. Initial
- 02
- Block Diagram
- 03
- Power Block Diagram
- 04
- IIC TREE
- 05
- Power IN
- 06
- Power Management
- 07
- BTB-200PIN
- 08
- USB2.0 Switch & RST Button
- 09
- USB2.0 HUB1
- 10
- USB2.0 HUB2 & USB A
- 11
- HDMI & CSI0
- 12
- IO Expand & 10/100M Ethernet
- 13
- Type-C Debug
- 14
- RTC & Encryption & EEPROM
- 15
- Mini PICe
- 16
- Gigabit PoE
- 17
- Terminal
- 18
- M.2 SSD
sheet 18
- Layout Note:
- Place 49.9R resistor near LAN9512
- I2C address : 0x21
